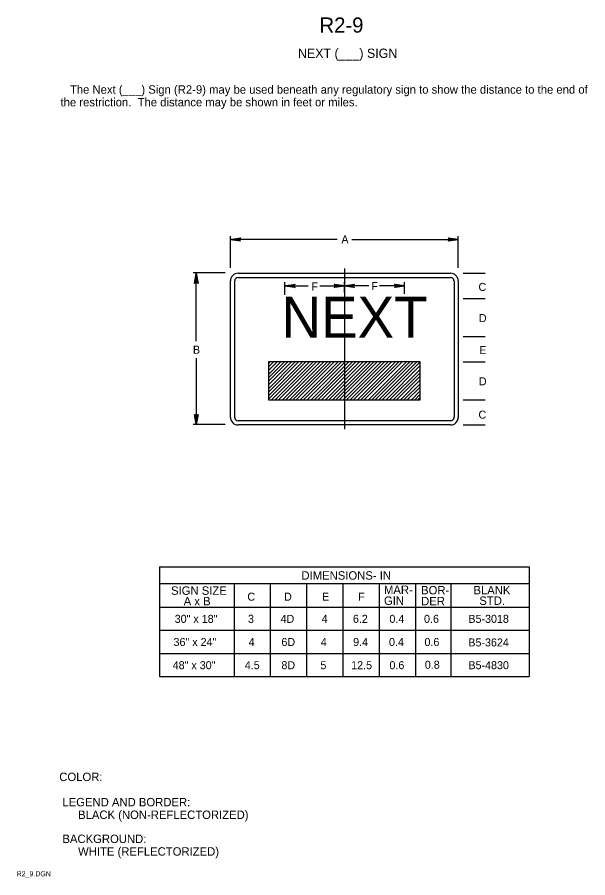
# Model space of a CAD drawing. Extents: x 0.013 to 0.182, y 0.004 to 0.259.
import ezdxf

# ---------------------------------------------------------------- set-up
doc = ezdxf.new("R2010")
doc.units = 0
for name, color, linetype in [('1', 7, 'Continuous'), ('2', 7, 'Continuous'), ('3', 7, 'Continuous')]:
    doc.layers.add(name, color=color, linetype=linetype)

# ---------------------------------------------------------------- blocks, each defined once
blk = doc.blocks.new('RARROW')
at = {"layer": '3'}
for p, q in [((-2.156, 0.285), (-2.2665, 0.384625)), ((-2.2665, 0.384625), (0, 0)), ((0, 0), (-2.2665, -0.379125)), ((-2.156, 0.285), (-2.075625, 0.12075)), ((0, 0), (-2.156, 0.285)), ((-2.14975, -0.2705), (0, 0)), ((-2.075625, 0.12075), (0, 0)), ((0, 0), (-2.074, -0.108)), ((-2.2665, -0.379125), (-2.14975, -0.2705)), ((-2.074, -0.108), (-2.14975, -0.2705))]:
    blk.add_line(p, q, dxfattribs=at)

msp = doc.modelspace()

# ---------------------------------------------------------------- linework, layer by layer
at = {"layer": '1'}
msp.add_line((0.10963, 0.18463), (0.10963, 0.137), dxfattribs=at)
at = {"layer": '3'}
for p, q in [((0.07587, 0.18488), (0.07587, 0.19425)), ((0.14338, 0.18488), (0.14338, 0.19425)), ((0.1075, 0.19325), (0.07587, 0.19325)), ((0.11188, 0.19325), (0.14338, 0.19325)), ((0.07426, 0.18337), (0.06479, 0.18337)), ((0.06575, 0.1631), (0.06575, 0.18337)), ((0.07812, 0.18325), (0.14112, 0.18325)), ((0.07812, 0.182), (0.14112, 0.182)), ((0.14488, 0.18325), (0.15138, 0.18325)), ((0.07587, 0.1405), (0.07587, 0.181)), ((0.07712, 0.1405), (0.07712, 0.181)), ((0.092, 0.17688), (0.092, 0.18063)), ((0.092, 0.1795), (0.09888, 0.1795)), ((0.10233, 0.1795), (0.10963, 0.1795)), ((0.10963, 0.1775), (0.10963, 0.18063)), ((0.11688, 0.1795), (0.10963, 0.1795)), ((0.1275, 0.1795), (0.12005, 0.1795)), ((0.1275, 0.17713), (0.1275, 0.18063)), ((0.14213, 0.181), (0.14213, 0.1405)), ((0.14338, 0.181), (0.14338, 0.1405)), ((0.14488, 0.17575), (0.15138, 0.17575)), ((0.14488, 0.1645), (0.15138, 0.1645)), ((0.06575, 0.15806), (0.06575, 0.13837)), ((0.08713, 0.1565), (0.08763, 0.157)), ((0.08713, 0.1555), (0.08862, 0.157)), ((0.08713, 0.15438), (0.08975, 0.157)), ((0.08713, 0.15325), (0.09075, 0.157)), ((0.08713, 0.15225), (0.09187, 0.157)), ((0.08713, 0.15125), (0.09287, 0.157)), ((0.08713, 0.15013), (0.094, 0.157)), ((0.08713, 0.149), (0.095, 0.157)), ((0.08713, 0.148), (0.096, 0.157)), ((0.08713, 0.14688), (0.09725, 0.157)), ((0.08713, 0.14588), (0.09825, 0.157)), ((0.088, 0.14575), (0.09925, 0.157)), ((0.08912, 0.14575), (0.10038, 0.157)), ((0.09012, 0.14575), (0.10138, 0.157)), ((0.09125, 0.14575), (0.1025, 0.157)), ((0.09225, 0.14575), (0.1035, 0.157)), ((0.09337, 0.14575), (0.10462, 0.157)), ((0.09438, 0.14575), (0.10562, 0.157)), ((0.09538, 0.14575), (0.10662, 0.157)), ((0.0965, 0.14575), (0.10775, 0.157)), ((0.0975, 0.14575), (0.10875, 0.157)), ((0.09863, 0.14575), (0.10988, 0.157)), ((0.09975, 0.14575), (0.111, 0.157)), ((0.10075, 0.14575), (0.112, 0.157)), ((0.10175, 0.14575), (0.113, 0.157)), ((0.10288, 0.14575), (0.11413, 0.157)), ((0.104, 0.14575), (0.11525, 0.157)), ((0.105, 0.14575), (0.11625, 0.157)), ((0.10612, 0.14575), (0.11738, 0.157)), ((0.10712, 0.14575), (0.11838, 0.157)), ((0.10812, 0.14575), (0.11938, 0.157)), ((0.10925, 0.14575), (0.1205, 0.157)), ((0.11025, 0.14575), (0.1215, 0.157)), ((0.11138, 0.14575), (0.12262, 0.157)), ((0.11238, 0.14575), (0.12362, 0.157)), ((0.1135, 0.14575), (0.12475, 0.157)), ((0.1145, 0.14575), (0.12575, 0.157)), ((0.1155, 0.14575), (0.12675, 0.157)), ((0.11675, 0.14575), (0.128, 0.157)), ((0.11775, 0.14575), (0.129, 0.157)), ((0.11875, 0.14575), (0.13, 0.157)), ((0.11988, 0.14575), (0.13112, 0.157)), ((0.12087, 0.14575), (0.13212, 0.157)), ((0.122, 0.14575), (0.13212, 0.15588)), ((0.13212, 0.157), (0.13212, 0.157)), ((0.14488, 0.157), (0.15138, 0.157)), ((0.123, 0.14575), (0.13212, 0.15475)), ((0.12412, 0.14575), (0.13212, 0.15375)), ((0.12513, 0.14575), (0.13212, 0.15275)), ((0.12625, 0.14575), (0.13212, 0.15163)), ((0.12725, 0.14575), (0.13212, 0.1505)), ((0.12825, 0.14575), (0.13212, 0.1495)), ((0.1295, 0.14575), (0.13212, 0.14838)), ((0.1305, 0.14575), (0.13212, 0.14738)), ((0.1315, 0.14575), (0.13212, 0.14638)), ((0.14488, 0.14575), (0.15138, 0.14575)), ((0.07426, 0.13837), (0.06479, 0.13837)), ((0.14112, 0.1395), (0.07812, 0.1395)), ((0.14112, 0.13825), (0.07812, 0.13825)), ((0.14488, 0.13825), (0.15138, 0.13825)), ((0.05488, 0.09613), (0.16437, 0.09613)), ((0.05488, 0.09613), (0.05488, 0.06363)), ((0.16437, 0.09613), (0.16437, 0.06363)), ((0.16437, 0.09112), (0.05488, 0.09112)), ((0.07692, 0.09112), (0.07692, 0.06362)), ((0.08767, 0.09112), (0.08767, 0.06362)), ((0.09842, 0.09112), (0.09842, 0.06362)), ((0.10917, 0.09112), (0.10917, 0.06362)), ((0.11992, 0.09112), (0.11992, 0.06362)), ((0.13067, 0.09112), (0.13067, 0.06362)), ((0.14117, 0.09112), (0.14117, 0.06362)), ((0.05488, 0.08425), (0.16437, 0.08425)), ((0.05488, 0.07737), (0.16437, 0.07737)), ((0.05488, 0.0705), (0.16437, 0.0705)), ((0.05488, 0.06363), (0.16437, 0.06363))]:
    msp.add_line(p, q, dxfattribs=at)
msp.add_lwpolyline([(0.08713, 0.14575), (0.13212, 0.14575), (0.13212, 0.157), (0.08713, 0.157)], close=True, dxfattribs=at)
for centre, radius, start, end in [((0.07812, 0.181), 0.00225, 90, 180), ((0.07812, 0.181), 0.001, 90, 180), ((0.14112, 0.181), 0.001, 0, 90), ((0.14112, 0.181), 0.00225, 0, 90), ((0.07812, 0.1405), 0.00225, 180, 270), ((0.07812, 0.1405), 0.001, 180, 270), ((0.14112, 0.1405), 0.00225, 270, 0), ((0.14112, 0.1405), 0.001, 270, 0)]:
    msp.add_arc(centre, radius, start, end, dxfattribs=at)

# ---------------------------------------------------------------- block references
at = {"layer": '3', "xscale": 0.0013236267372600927, "yscale": 0.001309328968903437}
for p, rotation in [((0.07587, 0.19325), 180), ((0.06575, 0.18325), 90), ((0.092, 0.1795), 180), ((0.10963, 0.1795), 180), ((0.06575, 0.13837), -90)]:
    msp.add_blockref('RARROW', p, dxfattribs=dict(at, rotation=rotation))
for p in [(0.14338, 0.19325), (0.10963, 0.1795), (0.1275, 0.1795)]:
    msp.add_blockref('RARROW', p, dxfattribs=at)

# ---------------------------------------------------------------- texts
at = {"layer": '1'}
for s, height, p in [('R2-9', 0.0045, (0.10225, 0.25462)), ('NEXT (___) SIGN ', 0.0027503, (0.09588, 0.24713)), ('COLOR:', 0.0025, (0.02513, 0.03263)), (' LEGEND AND BORDER:', 0.0024998, (0.02513, 0.02513)), ('      BLACK (NON-REFLECTORIZED)', 0.0024998, (0.02513, 0.02138)), (' BACKGROUND:', 0.0024998, (0.02513, 0.01425)), ('      WHITE (REFLECTORIZED)', 0.0024998, (0.02513, 0.0105)), ('R2_9.DGN', 0.0015, (0.0125, 0.00438))]:
    msp.add_text(s, height=height, dxfattribs=at).set_placement(p)
at = {"layer": '2'}
for s, height, p in [('   The Next (___) Sign (R2-9) may be used beneath any regulatory sign to show the distance to the end of', 0.00249975, (0.0255, 0.2365)), ('the restriction.  The distance may be shown in feet or miles.', 0.0024998, (0.0255, 0.23275))]:
    msp.add_text(s, height=height, dxfattribs=at).set_placement(p)
at = {"layer": '3'}
for s, height, p in [('A', 0.00238, (0.10875, 0.19212)), ('F', 0.00238, (0.09988, 0.17813)), ('F', 0.00238, (0.11763, 0.17825)), ('C', 0.00238, (0.14938, 0.178)), ('NEXT', 0.012137, (0.091, 0.16412)), ('D', 0.00238, (0.1495, 0.16875)), ('B', 0.00238, (0.06475, 0.15938)), ('E', 0.00238, (0.14963, 0.15925)), ('D', 0.00238, (0.1495, 0.15)), ('C', 0.00238, (0.14938, 0.14012)), ('DIMENSIONS- IN', 0.0024998, (0.0969, 0.09237)), ('SIGN SIZE', 0.0025, (0.05825, 0.08788)), ('MAR-', 0.0025, (0.12137, 0.08812)), ('BOR-', 0.0025, (0.13237, 0.088)), ('BLANK', 0.0025, (0.14788, 0.088)), ('A x B', 0.0025, (0.062, 0.08475)), ('C', 0.00238, (0.08088, 0.08613)), ('D', 0.00238, (0.09175, 0.08613)), ('E', 0.00238, (0.103, 0.08613)), ('F', 0.00238, (0.11375, 0.08613)), ('GIN', 0.0025, (0.12137, 0.08488)), ('DER', 0.0025, (0.13237, 0.08475)), ('STD.', 0.0025, (0.14963, 0.08488)), ('30" x 18"', 0.002375, (0.05934, 0.07956)), ('3', 0.00238, (0.08106, 0.07956)), ('4D', 0.002375, (0.09072, 0.07956)), ('4', 0.00238, (0.10289, 0.07956)), ('6.2', 0.002375, (0.11217, 0.07956)), ('0.4', 0.002375, (0.12298, 0.07956)), ('0.6', 0.002375, (0.13324, 0.07956)), ('B5-3018', 0.002375, (0.14638, 0.07956)), ('36" x 24"', 0.002375, (0.059, 0.07269)), ('4', 0.00238, (0.08126, 0.07269)), ('6D', 0.002375, (0.09097, 0.07269)), ('4', 0.00238, (0.10264, 0.07269)), ('9.4', 0.002375, (0.11223, 0.07269)), ('0.4', 0.002375, (0.12286, 0.07269)), ('0.6', 0.002375, (0.13337, 0.07269)), ('B5-3624', 0.002375, (0.14637, 0.07256)), ('48" x 30"', 0.002375, (0.05875, 0.06581)), ('4.5', 0.002375, (0.08012, 0.06581)), ('8D', 0.002375, (0.09097, 0.06581)), ('5', 0.00238, (0.10252, 0.06581)), ('12.5', 0.002375, (0.11165, 0.06581)), ('0.6', 0.002375, (0.12299, 0.06581)), ('0.8', 0.002375, (0.13348, 0.06594)), ('B5-4830', 0.002375, (0.1464, 0.06581))]:
    msp.add_text(s, height=height, dxfattribs=at).set_placement(p)

doc.saveas('drawing.dxf')
